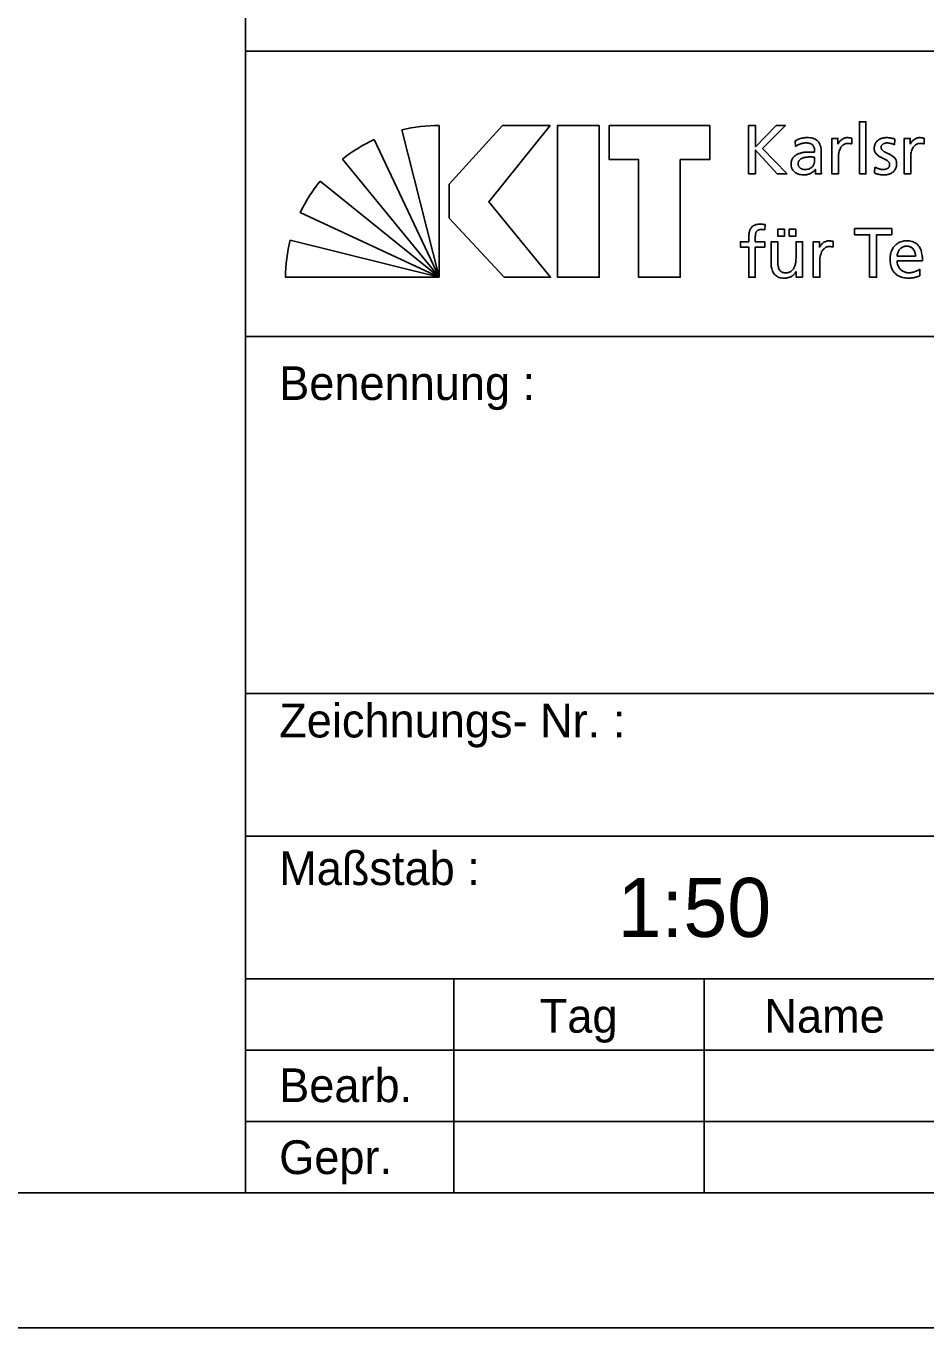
# Model space of a CAD drawing. Extents: x 0 to 21, y 0 to 14.9.
# Drawn here: x 15.75 to 18.416, y 0 to 3.858 of the extents above; entities that cross this region are included whole.
import ezdxf

# ---------------------------------------------------------------- set-up
doc = ezdxf.new("R2010")
doc.units = 0
doc.layers.add('90_Plankopf', color=7, linetype='Continuous')

msp = doc.modelspace()

# ---------------------------------------------------------------- linework, layer by layer
at = {"layer": '90_Plankopf'}
for p, q in [((16.4001, 3.784), (16.4001, 4.4185)), ((16.4001, 3.784), (20.6, 3.784)), ((16.8637, 3.5511), (16.974, 3.1138)), ((16.974, 3.1138), (16.974, 3.5637)), ((17.8905, 3.5638), (17.8905, 3.4198)), ((16.974, 3.1138), (16.7817, 3.5221)), ((18.029, 3.5176), (18.03, 3.5011)), ((18.1963, 3.5087), (18.1963, 3.5261)), ((18.3228, 3.5065), (18.3245, 3.5234)), ((18.4106, 3.5087), (18.4106, 3.5261)), ((18.1059, 3.4404), (18.1059, 3.484)), ((16.6872, 3.4638), (16.974, 3.1138)), ((18.0865, 3.4699), (18.0865, 3.4606)), ((18.2649, 3.4404), (18.2638, 3.4231)), ((16.974, 3.1138), (16.6217, 3.3988)), ((17.8905, 3.4198), (17.9111, 3.4198)), ((17.9753, 3.4198), (18.0054, 3.4198)), ((16.562, 3.3052), (16.974, 3.1138)), ((17.9387, 3.2541), (17.9395, 3.2698)), ((16.974, 3.1138), (16.5329, 3.2239)), ((18.1413, 3.2027), (18.1413, 3.2201)), ((18.3853, 3.1765), (18.3308, 3.1765)), ((18.3308, 3.1621), (18.4059, 3.1621)), ((18.3979, 3.1182), (18.3979, 3.1375)), ((16.5182, 3.1138), (16.974, 3.1138)), ((16.4001, 2.938), (20.6, 2.938)), ((16.4001, 1.8805), (20.6, 1.8805)), ((16.4001, 1.4575), (20.6, 1.4575)), ((16.4001, 1.0345), (20.6, 1.0345)), ((16.4001, 1.0345), (20.6, 1.0345)), ((16.4001, 1.0345), (20.6, 1.0345)), ((16.4001, 1.0345), (20.6, 1.0345)), ((16.4001, 0.4), (16.4001, 1.0345)), ((17.0176, 1.0345), (17.0176, 0.4)), ((17.7589, 0.4), (17.7589, 1.0345)), ((16.4001, 0.823), (18.5, 0.823)), ((16.4001, 0.6115), (18.5, 0.6115)), ((16.4001, 0.4), (20.6, 0.4)), ((16.4001, 0.4), (20.6, 0.4))]:
    msp.add_line(p, q, dxfattribs=at)
for points in [[(0, 0), (21, 0), (21, 14.85), (0, 14.85)], [(0.4, 0.4), (20.6, 0.4), (20.6, 14.45), (0.4, 14.45)], [(17.3033, 3.5638), (17.1618, 3.5638), (17.0036, 3.3894), (17.0036, 3.2891), (17.1669, 3.1138), (17.3042, 3.1138), (17.1211, 3.3376)], [(17.4485, 3.5638), (17.4485, 3.1138), (17.3251, 3.1138), (17.3251, 3.5638)], [(17.4781, 3.5638), (17.4781, 3.4625), (17.5651, 3.4625), (17.5651, 3.1138), (17.6885, 3.1138), (17.6885, 3.4625), (17.7755, 3.4625), (17.7755, 3.5638)]]:
    msp.add_lwpolyline(points, close=True, dxfattribs=at)
for points in [[(16.4001, 1.0345), (16.4001, 3.784)], [(18.0054, 3.4198), (17.9324, 3.4957), (18, 3.5638), (17.9726, 3.5638), (17.9111, 3.5005), (17.9111, 3.5638), (17.8905, 3.5638)], [(18.219, 3.4198), (18.2384, 3.4198), (18.2384, 3.5745), (18.219, 3.5745), (18.219, 3.4198)], [(18.1561, 3.5087), (18.1557, 3.5087), (18.1557, 3.525), (18.1375, 3.525), (18.1375, 3.4198), (18.1569, 3.4198), (18.1569, 3.4677)], [(18.3703, 3.5087), (18.3699, 3.5087), (18.3699, 3.525), (18.3518, 3.525), (18.3518, 3.4198), (18.3712, 3.4198), (18.3712, 3.4677)], [(17.9111, 3.4198), (17.9111, 3.4904), (17.9753, 3.4198)], [(18.0882, 3.4334), (18.0886, 3.4334), (18.0886, 3.4198), (18.1067, 3.4198)], [(17.9777, 3.2558), (17.9777, 3.2351), (17.9971, 3.2351), (17.9971, 3.2558), (17.9777, 3.2558)], [(18.0115, 3.2558), (18.0115, 3.2351), (18.0309, 3.2351), (18.0309, 3.2558), (18.0115, 3.2558)], [(18.2495, 3.1138), (18.2701, 3.1138), (18.2701, 3.2397), (18.3149, 3.2397), (18.3149, 3.2578), (18.2047, 3.2578), (18.2047, 3.2397), (18.2495, 3.2397), (18.2495, 3.1138)], [(17.8912, 3.2288), (17.8912, 3.2191), (17.8665, 3.2191), (17.8665, 3.2034), (17.8912, 3.2034), (17.8912, 3.1138), (17.9106, 3.1138), (17.9106, 3.2034), (17.9385, 3.2034), (17.9385, 3.2191), (17.9106, 3.2191), (17.9106, 3.2304)], [(17.9771, 3.1646), (17.9771, 3.2191), (17.9577, 3.2191), (17.9577, 3.1565)], [(18.0507, 3.1138), (18.0507, 3.2191), (18.0313, 3.2191), (18.0313, 3.1704)], [(18.1011, 3.2027), (18.1007, 3.2027), (18.1007, 3.2191), (18.0825, 3.2191), (18.0825, 3.1138), (18.1019, 3.1138), (18.1019, 3.1617)], [(18.0316, 3.1305), (18.032, 3.1305), (18.032, 3.1138), (18.0507, 3.1138)], [(20.6, 1.0345), (16.4001, 1.0345)], [(16.4001, 1.0345), (16.4001, 1.0345)], [(16.4001, 0.4), (20.6, 0.4)]]:
    msp.add_lwpolyline(points, dxfattribs=at)
for centre, start, end in [((16.9724, 3.0873), 89.8053, 103.1895), ((16.9831, 3.0904), 115.0126, 128.3968), ((16.9908, 3.0976), 140.7898, 154.174), ((16.9946, 3.1064), 165.7222, 179.1064)]:
    msp.add_arc(centre, 0.4764, start, end, dxfattribs=at)
for points in [[(18.1059, 3.484), (18.106, 3.4935), (18.1045, 3.5015), (18.1017, 3.508), (18.0988, 3.5145), (18.0942, 3.5193), (18.088, 3.5226), (18.0817, 3.5258), (18.0736, 3.5275), (18.0636, 3.5275), (18.0569, 3.5275), (18.0507, 3.5265), (18.0449, 3.5247), (18.0391, 3.5229), (18.0338, 3.5206), (18.029, 3.5176)], [(18.03, 3.5011), (18.0326, 3.5033), (18.0356, 3.5052), (18.039, 3.5068), (18.0423, 3.5084), (18.0458, 3.5096), (18.0495, 3.5105), (18.0532, 3.5114), (18.0568, 3.5118), (18.0605, 3.5118), (18.067, 3.5118), (18.0721, 3.5108), (18.0759, 3.5088), (18.0797, 3.5067), (18.0824, 3.5036), (18.0841, 3.4996), (18.0858, 3.4955), (18.0865, 3.4904), (18.0865, 3.4844)], [(18.1963, 3.5261), (18.195, 3.5263), (18.1937, 3.5266), (18.1925, 3.5268), (18.1912, 3.527), (18.1899, 3.5272), (18.1885, 3.5273), (18.1871, 3.5274), (18.1854, 3.5275), (18.1835, 3.5275), (18.1798, 3.5275), (18.1761, 3.5267), (18.1726, 3.5251), (18.1691, 3.5235), (18.1659, 3.5213), (18.163, 3.5184), (18.1601, 3.5156), (18.1578, 3.5124), (18.1561, 3.5087)], [(18.3245, 3.5234), (18.3207, 3.5245), (18.3169, 3.5255), (18.313, 3.5263), (18.3091, 3.5271), (18.3049, 3.5275), (18.3004, 3.5275), (18.2951, 3.5275), (18.2903, 3.5268), (18.2858, 3.5255), (18.2813, 3.5242), (18.2774, 3.5222), (18.274, 3.5195), (18.2706, 3.5168), (18.268, 3.5135), (18.2661, 3.5094), (18.2642, 3.5053), (18.2632, 3.5006), (18.2632, 3.4951), (18.2632, 3.4909), (18.2641, 3.4873), (18.2658, 3.4842), (18.2674, 3.4811), (18.2695, 3.4785), (18.2723, 3.4762), (18.275, 3.474), (18.2779, 3.472), (18.2812, 3.4702), (18.2844, 3.4685), (18.2876, 3.4669), (18.2909, 3.4654), (18.2941, 3.4638), (18.2971, 3.4622), (18.2998, 3.4606), (18.3025, 3.459), (18.3047, 3.4572), (18.3063, 3.4551), (18.3079, 3.4531), (18.3088, 3.4508), (18.3088, 3.4481), (18.3088, 3.4452), (18.3082, 3.4429), (18.307, 3.4409), (18.3058, 3.439), (18.3042, 3.4374), (18.3022, 3.4363), (18.3003, 3.4351), (18.2982, 3.4343), (18.2959, 3.4338), (18.2935, 3.4332), (18.2912, 3.433), (18.289, 3.433), (18.2871, 3.433), (18.2847, 3.4333), (18.282, 3.4338), (18.2792, 3.4344), (18.2763, 3.4352), (18.2733, 3.4363), (18.2703, 3.4374), (18.2675, 3.4388), (18.2649, 3.4404)], [(18.2638, 3.4231), (18.2683, 3.4208), (18.273, 3.4192), (18.2779, 3.4184), (18.2828, 3.4176), (18.2877, 3.4172), (18.2927, 3.4173), (18.2975, 3.4173), (18.302, 3.418), (18.3064, 3.4193), (18.3107, 3.4206), (18.3147, 3.4226), (18.3181, 3.4253), (18.3216, 3.428), (18.3243, 3.4314), (18.3264, 3.4355), (18.3284, 3.4396), (18.3294, 3.4445), (18.3295, 3.4501), (18.3294, 3.4549), (18.3286, 3.459), (18.3269, 3.4623), (18.3253, 3.4656), (18.3231, 3.4685), (18.3204, 3.4708), (18.3177, 3.4731), (18.3147, 3.4751), (18.3115, 3.4767), (18.3083, 3.4784), (18.305, 3.4799), (18.3018, 3.4813), (18.2986, 3.4828), (18.2956, 3.4843), (18.2929, 3.4858), (18.2902, 3.4874), (18.288, 3.4892), (18.2864, 3.4913), (18.2847, 3.4934), (18.2839, 3.496), (18.2838, 3.499), (18.2839, 3.5019), (18.2848, 3.5043), (18.2865, 3.5062), (18.2882, 3.5081), (18.2904, 3.5095), (18.2932, 3.5104), (18.296, 3.5114), (18.2991, 3.5118), (18.3024, 3.5118), (18.3036, 3.5118), (18.3051, 3.5116), (18.3069, 3.5114), (18.3088, 3.5111), (18.3107, 3.5106), (18.3127, 3.5101), (18.3148, 3.5096), (18.3167, 3.5091), (18.3185, 3.5084), (18.3203, 3.5078), (18.3217, 3.5071), (18.3228, 3.5065)], [(18.4106, 3.5261), (18.4092, 3.5263), (18.4079, 3.5266), (18.4067, 3.5268), (18.4055, 3.527), (18.4041, 3.5272), (18.4027, 3.5273), (18.4013, 3.5274), (18.3997, 3.5275), (18.3978, 3.5275), (18.394, 3.5275), (18.3904, 3.5267), (18.3868, 3.5251), (18.3833, 3.5235), (18.3801, 3.5213), (18.3773, 3.5184), (18.3744, 3.5156), (18.3721, 3.5124), (18.3703, 3.5087)], [(18.0865, 3.4844), (18.084, 3.4845), (18.0817, 3.4846), (18.0795, 3.4846), (18.0773, 3.4847), (18.0751, 3.4848), (18.0729, 3.4848), (18.0708, 3.4848), (18.0684, 3.4848), (18.0659, 3.4848), (18.0618, 3.4848), (18.0576, 3.4844), (18.0531, 3.4837), (18.0487, 3.483), (18.0443, 3.4818), (18.04, 3.4802), (18.0358, 3.4786), (18.0319, 3.4764), (18.0284, 3.4737), (18.025, 3.4711), (18.0222, 3.4678), (18.0201, 3.4639), (18.0181, 3.46), (18.0171, 3.4554), (18.017, 3.4501), (18.0171, 3.4425), (18.0187, 3.4363), (18.0219, 3.4314), (18.0252, 3.4266), (18.0297, 3.423), (18.0355, 3.4207), (18.0413, 3.4184), (18.0479, 3.4173), (18.0556, 3.4173), (18.06, 3.4173), (18.064, 3.4179), (18.0675, 3.4189), (18.071, 3.42), (18.0741, 3.4213), (18.0768, 3.4229), (18.0795, 3.4246), (18.0818, 3.4264), (18.0837, 3.4282), (18.0855, 3.43), (18.087, 3.4317), (18.0882, 3.4334)], [(18.1569, 3.4677), (18.1569, 3.4765), (18.1581, 3.4841), (18.1605, 3.4905), (18.1629, 3.4969), (18.1662, 3.5019), (18.1705, 3.5053), (18.1747, 3.5088), (18.1798, 3.5105), (18.1856, 3.5106), (18.1873, 3.5106), (18.189, 3.5105), (18.1909, 3.5102), (18.1927, 3.5099), (18.1945, 3.5094), (18.1963, 3.5087)], [(18.3712, 3.4677), (18.3712, 3.4765), (18.3724, 3.4841), (18.3747, 3.4905), (18.3771, 3.4969), (18.3804, 3.5019), (18.3847, 3.5053), (18.389, 3.5088), (18.394, 3.5105), (18.3998, 3.5106), (18.4015, 3.5106), (18.4033, 3.5105), (18.4051, 3.5102), (18.407, 3.5099), (18.4088, 3.5094), (18.4106, 3.5087)], [(18.0865, 3.4606), (18.0865, 3.4554), (18.0854, 3.4506), (18.0832, 3.4465), (18.081, 3.4423), (18.0777, 3.4391), (18.0733, 3.4367), (18.069, 3.4343), (18.0636, 3.433), (18.0572, 3.433), (18.055, 3.433), (18.0527, 3.4334), (18.0504, 3.4341), (18.0481, 3.4348), (18.046, 3.4359), (18.0441, 3.4374), (18.0422, 3.4388), (18.0406, 3.4406), (18.0394, 3.4427), (18.0383, 3.4449), (18.0377, 3.4473), (18.0376, 3.4501), (18.0377, 3.4538), (18.0386, 3.4569), (18.0404, 3.4594), (18.0422, 3.4618), (18.0446, 3.4638), (18.0475, 3.4652), (18.0503, 3.4667), (18.0534, 3.4678), (18.0567, 3.4686), (18.06, 3.4693), (18.0632, 3.4698), (18.0663, 3.47), (18.0694, 3.4703), (18.072, 3.4704), (18.0741, 3.4703), (18.0762, 3.4703), (18.0783, 3.4703), (18.0803, 3.4701), (18.0824, 3.47), (18.0845, 3.47), (18.0865, 3.4699)], [(18.1067, 3.4198), (18.1066, 3.4208), (18.1065, 3.4222), (18.1063, 3.4238), (18.1062, 3.4256), (18.1061, 3.4278), (18.1061, 3.4305), (18.106, 3.4331), (18.1059, 3.4365), (18.1059, 3.4404)], [(17.9395, 3.2698), (17.9375, 3.2701), (17.9355, 3.2704), (17.9334, 3.2707), (17.9312, 3.2709), (17.929, 3.2711), (17.9265, 3.2711), (17.9194, 3.271), (17.9135, 3.27), (17.9089, 3.2681), (17.9043, 3.2661), (17.9007, 3.2632), (17.8981, 3.2595), (17.8955, 3.2558), (17.8937, 3.2513), (17.8927, 3.2461), (17.8917, 3.241), (17.8912, 3.2352), (17.8912, 3.2288)], [(17.9106, 3.2304), (17.9106, 3.234), (17.9108, 3.2373), (17.9112, 3.2403), (17.9116, 3.2433), (17.9125, 3.246), (17.9137, 3.2482), (17.915, 3.2505), (17.9169, 3.2522), (17.9194, 3.2535), (17.9219, 3.2547), (17.9252, 3.2554), (17.9294, 3.2554), (17.9311, 3.2554), (17.9328, 3.2553), (17.9344, 3.2551), (17.9361, 3.2548), (17.9375, 3.2545), (17.9387, 3.2541)], [(18.1413, 3.2201), (18.14, 3.2204), (18.1387, 3.2206), (18.1375, 3.2208), (18.1363, 3.221), (18.1349, 3.2212), (18.1335, 3.2213), (18.1321, 3.2215), (18.1304, 3.2215), (18.1286, 3.2215), (18.1248, 3.2215), (18.1212, 3.2207), (18.1176, 3.2191), (18.1141, 3.2175), (18.1109, 3.2153), (18.1081, 3.2125), (18.1052, 3.2097), (18.1029, 3.2064), (18.1011, 3.2027)], [(18.1019, 3.1617), (18.102, 3.1705), (18.1032, 3.1782), (18.1055, 3.1846), (18.1079, 3.191), (18.1112, 3.1959), (18.1155, 3.1993), (18.1198, 3.2028), (18.1248, 3.2046), (18.1306, 3.2046), (18.1323, 3.2046), (18.1341, 3.2045), (18.1359, 3.2042), (18.1378, 3.204), (18.1396, 3.2035), (18.1413, 3.2027)], [(18.4059, 3.1621), (18.406, 3.1706), (18.4052, 3.1785), (18.4036, 3.1857), (18.402, 3.1929), (18.3995, 3.1991), (18.3959, 3.2045), (18.3923, 3.2099), (18.3875, 3.214), (18.3815, 3.217), (18.3756, 3.22), (18.3682, 3.2215), (18.3595, 3.2215), (18.352, 3.2215), (18.3453, 3.2202), (18.3392, 3.2176), (18.3332, 3.215), (18.328, 3.2114), (18.3237, 3.2066), (18.3194, 3.2019), (18.316, 3.1963), (18.3137, 3.1897), (18.3114, 3.1833), (18.3102, 3.1761), (18.3102, 3.1683), (18.3102, 3.1597), (18.3113, 3.1519), (18.3134, 3.1449), (18.3156, 3.138), (18.319, 3.132), (18.3234, 3.127), (18.3279, 3.122), (18.3335, 3.1181), (18.3404, 3.1154), (18.3473, 3.1127), (18.3553, 3.1114), (18.3647, 3.1113), (18.3704, 3.1114), (18.3753, 3.1118), (18.3793, 3.1125), (18.3834, 3.1133), (18.3869, 3.1142), (18.3898, 3.1152), (18.3928, 3.1162), (18.3954, 3.1172), (18.3979, 3.1182)], [(18.3308, 3.1765), (18.3312, 3.18), (18.332, 3.1834), (18.3332, 3.1869), (18.3344, 3.1903), (18.3361, 3.1934), (18.3384, 3.1963), (18.3406, 3.1992), (18.3434, 3.2015), (18.3469, 3.2032), (18.3503, 3.2049), (18.3543, 3.2058), (18.3591, 3.2058), (18.3633, 3.2058), (18.367, 3.2051), (18.3702, 3.2035), (18.3735, 3.202), (18.3762, 3.1999), (18.3785, 3.1972), (18.3807, 3.1946), (18.3824, 3.1914), (18.3835, 3.1879), (18.3847, 3.1844), (18.3853, 3.1806), (18.3853, 3.1765)], [(18.0313, 3.1704), (18.0313, 3.1639), (18.0307, 3.1581), (18.0295, 3.1528), (18.0282, 3.1475), (18.0263, 3.1429), (18.0236, 3.1391), (18.021, 3.1352), (18.0177, 3.1323), (18.0137, 3.1302), (18.0096, 3.1281), (18.0049, 3.1271), (17.9994, 3.127), (17.9938, 3.1274), (17.9893, 3.1289), (17.9861, 3.1318), (17.9828, 3.1346), (17.9805, 3.1387), (17.9791, 3.1442), (17.9777, 3.1496), (17.9771, 3.1564), (17.9771, 3.1646)], [(17.9577, 3.1565), (17.9577, 3.1471), (17.9591, 3.139), (17.9618, 3.1323), (17.9646, 3.1255), (17.969, 3.1204), (17.9748, 3.1168), (17.9806, 3.1132), (17.988, 3.1114), (17.9971, 3.1113), (18.002, 3.1114), (18.0068, 3.1121), (18.0113, 3.1136), (18.0158, 3.1152), (18.0198, 3.1174), (18.0233, 3.1202), (18.0268, 3.1231), (18.0296, 3.1265), (18.0316, 3.1305)], [(18.3979, 3.1375), (18.3967, 3.1366), (18.3949, 3.1355), (18.3926, 3.1342), (18.3903, 3.133), (18.3877, 3.1319), (18.3847, 3.1308), (18.3817, 3.1297), (18.3786, 3.1288), (18.3753, 3.1281), (18.372, 3.1274), (18.3687, 3.1271), (18.3655, 3.127), (18.3608, 3.1271), (18.3565, 3.1279), (18.3523, 3.1296), (18.3482, 3.1313), (18.3445, 3.1337), (18.3413, 3.1368), (18.338, 3.1399), (18.3355, 3.1435), (18.3336, 3.1478), (18.3318, 3.1521), (18.3309, 3.1569), (18.3308, 3.1621)]]:
    msp.add_open_spline(points, degree=3, dxfattribs=at)

# ---------------------------------------------------------------- texts
for s, height, p in [('Benennung :', 0.1, (16.5, 2.75)), ('Zeichnungs- Nr. :', 0.1, (16.5, 1.75)), ('Maßstab :', 0.1, (16.5, 1.3125)), ('1:50    ', 0.175, (17.5024, 1.1587)), ('Tag', 0.1, (17.2721, 0.875)), ('Name', 0.1, (17.9375, 0.875)), ('Bearb.', 0.1, (16.5, 0.6692)), ('Gepr.', 0.1, (16.5, 0.4561))]:
    msp.add_text(s, height=height, dxfattribs=at).set_placement(p)

doc.saveas('drawing.dxf')
